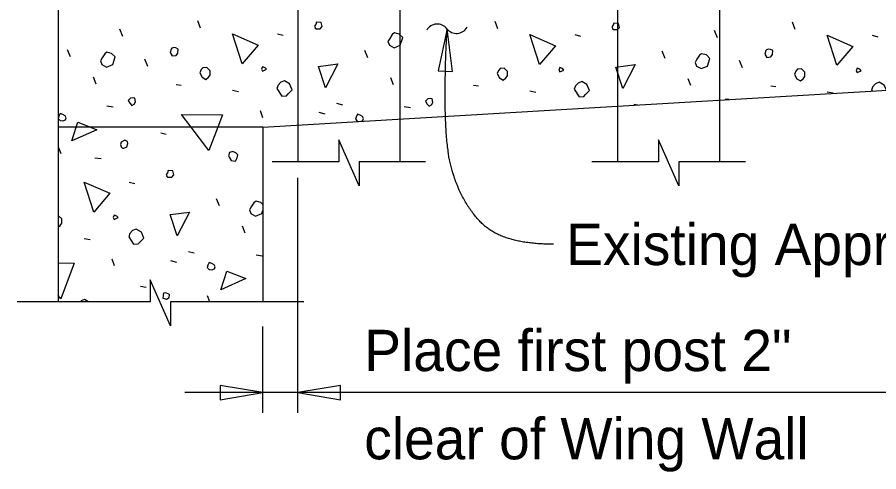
# Model space of a CAD drawing. Extents: x 0 to 41.1, y 0 to 26.
# Drawn here: x 5.557 to 9.767, y 8.26 to 10.482 of the extents above; entities that cross this region are included whole.
import ezdxf

# ---------------------------------------------------------------- set-up
doc = ezdxf.new("R2010")
doc.units = 0
for name, color, linetype in [('Dimension', 7, 'Continuous'), ('Miscellaneous', 7, 'Continuous'), ('TextStructures', 7, 'Continuous'), ('TrafBarrierConc', 7, 'Continuous')]:
    doc.layers.add(name, color=color, linetype=linetype)

msp = doc.modelspace()

# ---------------------------------------------------------------- linework, layer by layer
at = {"layer": 'Dimension'}
for p, q in [((6.9275, 8.5474), (6.9275, 9.6964)), ((6.7566, 8.5474), (6.7566, 8.9699)), ((10.272, 8.6469), (6.3751, 8.6469))]:
    msp.add_line(p, q, dxfattribs=at)
for points in [[(7.6573, 10.4257), (7.6135, 10.2191), (7.684, 10.2162)], [(6.7567, 8.6469), (6.5484, 8.6822), (6.5484, 8.6116)], [(6.9276, 8.6469), (7.1358, 8.6116), (7.1358, 8.6822)]]:
    msp.add_lwpolyline(points, close=True, dxfattribs=at)
for points in [[(7.5526, 9.7744), (7.2273, 9.7744), (7.2273, 9.6582), (7.1279, 9.8832), (7.1279, 9.7744), (6.8026, 9.7744)], [(9.1151, 9.7744), (8.7898, 9.7744), (8.7898, 9.6582), (8.6904, 9.8832), (8.6904, 9.7744), (8.3651, 9.7744)], [(6.9567, 9.0899), (6.3064, 9.0899), (6.3064, 8.9736), (6.207, 9.1986), (6.207, 9.0899), (5.5567, 9.0899)]]:
    msp.add_lwpolyline(points, dxfattribs=at)
for centre, start, end in [((7.6096, 10.3888), 38.2108, 149.938), ((7.7032, 10.4626), 218.2108, 329.938)]:
    msp.add_arc(centre, 0.0596, start, end, dxfattribs=at)
msp.add_open_spline([(8.1779, 9.372), (7.9318, 9.372), (7.7267, 9.5727), (7.631, 9.9148), (7.6572, 10.4257)], degree=2, dxfattribs=at)
at = {"layer": 'Miscellaneous'}
for p, q in [((6.4531, 10.4289), (6.439, 10.4643)), ((7.9062, 10.4254), (7.8921, 10.4608)), ((9.3593, 10.4219), (9.3452, 10.4572)), ((6.073, 10.3883), (6.0589, 10.4236)), ((6.8279, 10.4007), (6.8562, 10.3936)), ((8.9793, 10.3812), (8.9651, 10.4166)), ((8.281, 10.3971), (8.3093, 10.39)), ((9.7341, 10.3936), (9.7624, 10.3865)), ((5.8167, 10.2875), (5.8026, 10.3229)), ((7.2698, 10.284), (7.2557, 10.3193)), ((8.7229, 10.2804), (8.7088, 10.3158)), ((6.195, 10.2416), (6.1809, 10.2769)), ((9.1012, 10.2345), (9.0871, 10.2698)), ((5.9422, 10.1549), (5.9299, 10.1885)), ((6.3329, 10.1532), (6.3577, 10.1496)), ((7.3953, 10.1514), (7.383, 10.185)), ((7.786, 10.1496), (7.8108, 10.1461)), ((8.8484, 10.1479), (8.8361, 10.1814)), ((6.6087, 10.1249), (6.6387, 10.1196)), ((8.0618, 10.1213), (8.0918, 10.116)), ((9.2391, 10.1461), (9.2639, 10.1426)), ((9.5149, 10.1178), (9.5449, 10.1125)), ((5.9953, 10.0489), (6.0253, 10.0436)), ((6.7572, 9.9905), (6.7448, 10.0241)), ((7.1178, 10.0612), (7.1461, 10.0542)), ((7.4484, 10.0453), (7.4784, 10.04)), ((8.5709, 10.0577), (8.5891, 10.0532)), ((7.0312, 10.017), (7.0595, 10.01)), ((6.2587, 9.9163), (6.2852, 9.911)), ((5.7708, 9.8138), (5.7584, 9.8473)), ((5.9352, 9.7943), (5.967, 9.7908)), ((6.1031, 9.6759), (6.1314, 9.6688)), ((6.545, 9.5592), (6.5309, 9.5945)), ((6.6705, 9.4266), (6.6582, 9.4602)), ((5.8839, 9.4001), (5.9139, 9.3948)), ((6.393, 9.3365), (6.4213, 9.3294)), ((6.7236, 9.3205), (6.7536, 9.3152)), ((6.0324, 9.2657), (6.02, 9.2993)), ((6.3064, 9.2923), (6.3347, 9.2852)), ((6.1597, 9.1668), (6.1862, 9.1614)), ((6.4974, 9.0899), (6.4867, 9.119))]:
    msp.add_line(p, q, dxfattribs=at)
for points in [[(7.4275, 9.7744), (7.4275, 13.5946), (6.9275, 13.5946), (6.9275, 9.7744)], [(8.99, 9.7744), (8.99, 13.5946), (8.49, 13.5946), (8.49, 9.7744)], [(7.0153, 10.4254), (7.0365, 10.4254), (7.0471, 10.436), (7.0418, 10.4555), (7.0188, 10.4572), (7.0153, 10.4466), (7.01, 10.4378), (7.0153, 10.4254), (7.0117, 10.4289)], [(8.4684, 10.4219), (8.4896, 10.4219), (8.5002, 10.4325), (8.4949, 10.4519), (8.4719, 10.4537), (8.4684, 10.4431), (8.4631, 10.4342), (8.4684, 10.4219), (8.4648, 10.4254)], [(6.6564, 10.2539), (6.6087, 10.4007), (6.7342, 10.3459), (6.6564, 10.2539)], [(7.3756, 10.345), (7.3986, 10.3326), (7.4286, 10.345), (7.441, 10.3821), (7.4233, 10.3998), (7.4004, 10.4051), (7.3898, 10.398), (7.3774, 10.3786), (7.3685, 10.3627), (7.3756, 10.345)], [(8.1095, 10.2504), (8.0618, 10.3971), (8.1873, 10.3423), (8.1095, 10.2504)], [(9.5626, 10.2469), (9.5149, 10.3936), (9.6404, 10.3388), (9.5626, 10.2469)], [(6.3046, 10.3087), (6.3135, 10.2928), (6.3329, 10.2946), (6.3417, 10.307), (6.3435, 10.3264), (6.3311, 10.3317), (6.3223, 10.3335), (6.3117, 10.3299), (6.3082, 10.3264), (6.3046, 10.3087)], [(9.2108, 10.3017), (9.2197, 10.2857), (9.2391, 10.2875), (9.248, 10.2999), (9.2497, 10.3193), (9.2373, 10.3246), (9.2285, 10.3264), (9.2179, 10.3229), (9.2144, 10.3193), (9.2108, 10.3017)], [(5.9705, 10.2504), (5.9935, 10.238), (6.0235, 10.2504), (6.0359, 10.2875), (6.0182, 10.3052), (5.9953, 10.3105), (5.9847, 10.3034), (5.9723, 10.284), (5.9634, 10.2681), (5.9705, 10.2504)], [(8.8767, 10.2433), (8.8997, 10.2309), (8.9298, 10.2433), (8.9421, 10.2804), (8.9245, 10.2981), (8.9015, 10.3034), (8.8909, 10.2964), (8.8785, 10.2769), (8.8697, 10.261), (8.8767, 10.2433)], [(6.4496, 10.2097), (6.4602, 10.1885), (6.4779, 10.1779), (6.492, 10.1885), (6.4991, 10.1991), (6.4991, 10.2203), (6.4832, 10.2362), (6.4637, 10.2345), (6.4549, 10.2256), (6.4496, 10.2097)], [(6.7554, 10.2186), (6.7748, 10.2274), (6.7678, 10.2345), (6.7554, 10.2398), (6.7501, 10.2274), (6.7554, 10.2186)], [(7.063, 10.1373), (7.0294, 10.2416), (7.1231, 10.2539), (7.063, 10.1373)], [(7.9027, 10.2062), (7.9133, 10.185), (7.931, 10.1744), (7.9451, 10.185), (7.9522, 10.1956), (7.9522, 10.2168), (7.9363, 10.2327), (7.9168, 10.2309), (7.908, 10.2221), (7.9027, 10.2062)], [(8.2085, 10.215), (8.228, 10.2239), (8.2209, 10.2309), (8.2085, 10.2362), (8.2032, 10.2239), (8.2085, 10.215)], [(8.5161, 10.1337), (8.4825, 10.238), (8.5762, 10.2504), (8.5161, 10.1337)], [(9.6616, 10.2115), (9.6811, 10.2203), (9.674, 10.2274), (9.6616, 10.2327), (9.6563, 10.2203), (9.6616, 10.2115)], [(9.3558, 10.2027), (9.3664, 10.1814), (9.3841, 10.1708), (9.3982, 10.1814), (9.4053, 10.1921), (9.4053, 10.2133), (9.3894, 10.2292), (9.3699, 10.2274), (9.3611, 10.2186), (9.3558, 10.2027)], [(6.8261, 10.1337), (6.8491, 10.0966), (6.8721, 10.0984), (6.8809, 10.1072), (6.9004, 10.1266), (6.888, 10.1567), (6.8632, 10.1708), (6.8456, 10.1638), (6.8314, 10.1496), (6.8261, 10.1337)], [(8.2792, 10.1302), (8.3022, 10.0931), (8.3252, 10.0948), (8.334, 10.1037), (8.3535, 10.1231), (8.3411, 10.1532), (8.3163, 10.1673), (8.2987, 10.1602), (8.2845, 10.1461), (8.2792, 10.1302)], [(9.8043, 10.1252), (9.7942, 10.1496), (9.7694, 10.1638), (9.7518, 10.1567), (9.7376, 10.1426), (9.7323, 10.1266)], [(9.7323, 10.1266), (9.7358, 10.1211)], [(6.1066, 10.0612), (6.1172, 10.0506), (6.1278, 10.0577), (6.1349, 10.0683), (6.1314, 10.086), (6.1225, 10.0878), (6.1102, 10.086), (6.0996, 10.0754), (6.1066, 10.0612)], [(7.5597, 10.0577), (7.5703, 10.0471), (7.5809, 10.0542), (7.588, 10.0648), (7.5845, 10.0825), (7.5756, 10.0842), (7.5633, 10.0825), (7.5527, 10.0718), (7.5597, 10.0577)], [(9.0344, 10.0795), (9.0288, 10.0807), (9.0164, 10.0789), (9.0159, 10.0784)], [(5.7672, 9.9764), (5.7796, 9.9746), (5.792, 9.9799), (5.7955, 9.9905), (5.7902, 9.9994), (5.7796, 10.0064), (5.7672, 10.0117), (5.7601, 9.9976), (5.7566, 9.987)], [(5.7566, 9.987), (5.7672, 9.9764)], [(6.4064, 9.9446), (6.3594, 10.0064), (6.5592, 10.0047), (6.5367, 9.9446)], [(7.2373, 9.9731), (7.2451, 9.9764), (7.2486, 9.987), (7.2433, 9.9958), (7.2327, 10.0029), (7.2203, 10.0082), (7.2133, 9.9941), (7.2097, 9.9835), (7.2203, 9.9729)], [(5.8238, 9.8774), (5.8445, 9.9446)], [(5.9145, 9.9446), (5.9458, 9.9322), (5.8238, 9.8774)], [(5.8445, 9.9446), (5.8521, 9.9693), (5.9145, 9.9446)], [(6.4938, 9.8297), (6.4064, 9.9446)], [(6.5367, 9.9446), (6.4938, 9.8297)], [(7.2203, 9.9729), (7.2242, 9.9723)], [(6.0713, 9.842), (6.0783, 9.842), (6.0925, 9.8491), (6.0978, 9.865), (6.096, 9.8739), (6.0819, 9.8809), (6.0642, 9.8703), (6.0607, 9.8597), (6.0642, 9.8491), (6.0713, 9.842)], [(6.5928, 9.7978), (6.6016, 9.7819), (6.6228, 9.7784), (6.6317, 9.7943), (6.6352, 9.8084), (6.6264, 9.8173), (6.6104, 9.8261), (6.5945, 9.8208), (6.5892, 9.8049), (6.5928, 9.7978)], [(6.2905, 9.7006), (6.3117, 9.7006), (6.3223, 9.7112), (6.317, 9.7307), (6.294, 9.7324), (6.2905, 9.7218), (6.2852, 9.713), (6.2905, 9.7006), (6.2869, 9.7042)], [(5.9316, 9.5291), (5.8839, 9.6759), (6.0094, 9.6211), (5.9316, 9.5291)], [(6.7566, 9.5668), (6.7466, 9.5769), (6.7236, 9.5822), (6.713, 9.5751), (6.7006, 9.5557), (6.6918, 9.5397), (6.6988, 9.5221)], [(6.3382, 9.4125), (6.3046, 9.5168), (6.3983, 9.5291), (6.3382, 9.4125)], [(6.6988, 9.5221), (6.7218, 9.5097), (6.7519, 9.5221), (6.7566, 9.5363)], [(5.7566, 9.4558), (5.7672, 9.4637), (5.7743, 9.4743), (5.7743, 9.4956), (5.7584, 9.5115), (5.7566, 9.5113)], [(6.0306, 9.4938), (6.0501, 9.5026), (6.043, 9.5097), (6.0306, 9.515), (6.0253, 9.5026), (6.0306, 9.4938)], [(6.1013, 9.4089), (6.1243, 9.3718), (6.1473, 9.3736), (6.1561, 9.3824), (6.1756, 9.4019), (6.1632, 9.4319), (6.1385, 9.4461), (6.1208, 9.439), (6.1066, 9.4248), (6.1013, 9.4089)], [(5.7566, 9.2806), (5.8344, 9.2799), (5.769, 9.1049)], [(6.4955, 9.2481), (6.5079, 9.2463), (6.5203, 9.2516), (6.5238, 9.2622), (6.5185, 9.271), (6.5079, 9.2781), (6.4955, 9.2834), (6.4885, 9.2693), (6.4849, 9.2587), (6.4955, 9.2481)], [(6.5521, 9.1491), (6.5804, 9.241), (6.6741, 9.2039), (6.5521, 9.1491)], [(5.769, 9.1049), (5.7566, 9.1212)], [(5.9042, 9.0899), (5.9016, 9.0925), (5.8857, 9.1013), (5.8698, 9.096), (5.8677, 9.0899)], [(6.2675, 9.1084), (6.2869, 9.1031), (6.2993, 9.1119), (6.3011, 9.1243), (6.2976, 9.1279), (6.2834, 9.1349), (6.271, 9.1332), (6.2693, 9.1208), (6.2675, 9.1084)]]:
    msp.add_lwpolyline(points, dxfattribs=at)
at = {"layer": 'TrafBarrierConc'}
for p, q in [((5.7567, 11.6946), (5.7567, 9.0899)), ((6.7566, 9.9446), (10.9766, 10.1946)), ((6.7566, 9.9446), (5.7566, 9.9446)), ((6.7567, 9.9446), (6.7567, 9.0899))]:
    msp.add_line(p, q, dxfattribs=at)

# ---------------------------------------------------------------- texts
at = {"layer": 'TextStructures'}
for s, p in [('Existing Approach Slab', (8.2391, 9.2703)), ('Place first post 2"', (7.2524, 8.752)), ('clear of Wing Wall', (7.2524, 8.3204))]:
    msp.add_text(s, height=0.2016, dxfattribs=at).set_placement(p)

doc.saveas('drawing.dxf')
